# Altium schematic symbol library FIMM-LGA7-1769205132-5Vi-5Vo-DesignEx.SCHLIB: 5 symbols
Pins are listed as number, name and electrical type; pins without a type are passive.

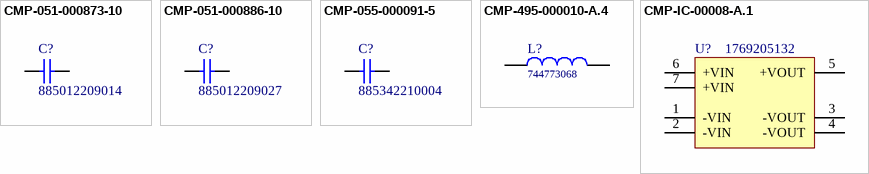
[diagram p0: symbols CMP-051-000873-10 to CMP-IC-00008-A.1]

## CMP-051-000873-10
designator C?, comment 885012209014
WCAP-CSGP Multilayer Ceramic Chip Capacitor, General Purpose, size 1210, X7R, 10uF, 16V; Manufacturer: Wurth Electronics; Technical Reference: X7R1210106K016DFCT10000; Isolation Resistance: >=0.1GOhm; Rated Voltage: 16VDC; Capacitance Tolerance: +/-10%
footprint WCAP-CSGP_1210_H=2mm (Ceramic Capacitors, body 3.2x2.5mm)
footprint SMD MLCC 1210 IPC Generator (Chip Capacitor, 2-Leads, Body 3,20x2,50mm, IPC Medium Density)
pins: 1, 2

## CMP-051-000886-10
designator C?, comment 885012209027
WCAP-CSGP Multilayer Ceramic Chip Capacitor, General Purpose, size 1210, X7R, 4.7uF, 25V; Manufacturer: Wurth Electronics; Capacitance Tolerance: +/-10%; Isolation Resistance: >=0.1GOhm; Technical Reference: X7R1210475K025DFCT10000; Rated Voltage: 25VDC
footprint WCAP-CSGP_1210_H=2mm (Ceramic Capacitors, body 3.2x2.5mm)
footprint SMD MLCC 1210 IPC Generator (Chip Capacitor, 2-Leads, Body 3,20x2,50mm, IPC Medium Density)
pins: 1, 2

## CMP-055-000091-5
designator C?, comment 885342210004
WCAP-CSMH Multilayer Ceramic Chip Capacitor, size 1808, X7R Class II, 1nF, 3000V; Manufacturer: Wurth Electronics; Technical Reference: X7R1808102KC00DFCT10000; Rated Voltage: 3000VDC; Insulation Resistance: 10GOhm; Provided by WE: Yes; Capacitance Tolerance: +/-10%; Dissipation Factor: 2.5%
footprint WCAP-CSMH_1808_H2 (Ceramic Capacitors, body 4.5x2.03mm)
pins: 1, 2

## CMP-495-000010-A.4
designator L?, comment 744773068
WE-PD2 SMT Power Inductor, size 4532, 6.8uH, 1.54A; Manufacturer: Wurth Elektronik; Manufacturer: Wurth Electronics; DC Resistance typ.: 0.076Ohm; Self Resonant Frequency: 41MHz; Saturation Current: 2.1A; DC Resistance max.: 0.131Ohm
footprint WE-PD2_4532 (SMD Power Inductor, 2-Leads, body 4x4.5mm)
pins: 1, 2

## CMP-IC-00008-A.1
designator U?, comment 1769205132
WPME-FIMM Fixed Isolated Module, LGA-7, 4.5-5.5Vin, 5Vout; Manufacturer: Wurth Elektronik; Isolation Voltage: 3kV; Output Voltage: 5V; Input Voltage Max: 5.5V; Input Voltage Min: 4.5V
footprint WPME-FIMM_LGA-7_L9W7H3.1 (Power Module, SMT, body 9.00x7.00mm)
pins: 1 -VIN, 2 -VIN, 3 -VOUT, 4 -VOUT, 5 +VOUT, 6 +VIN, 7 +VIN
